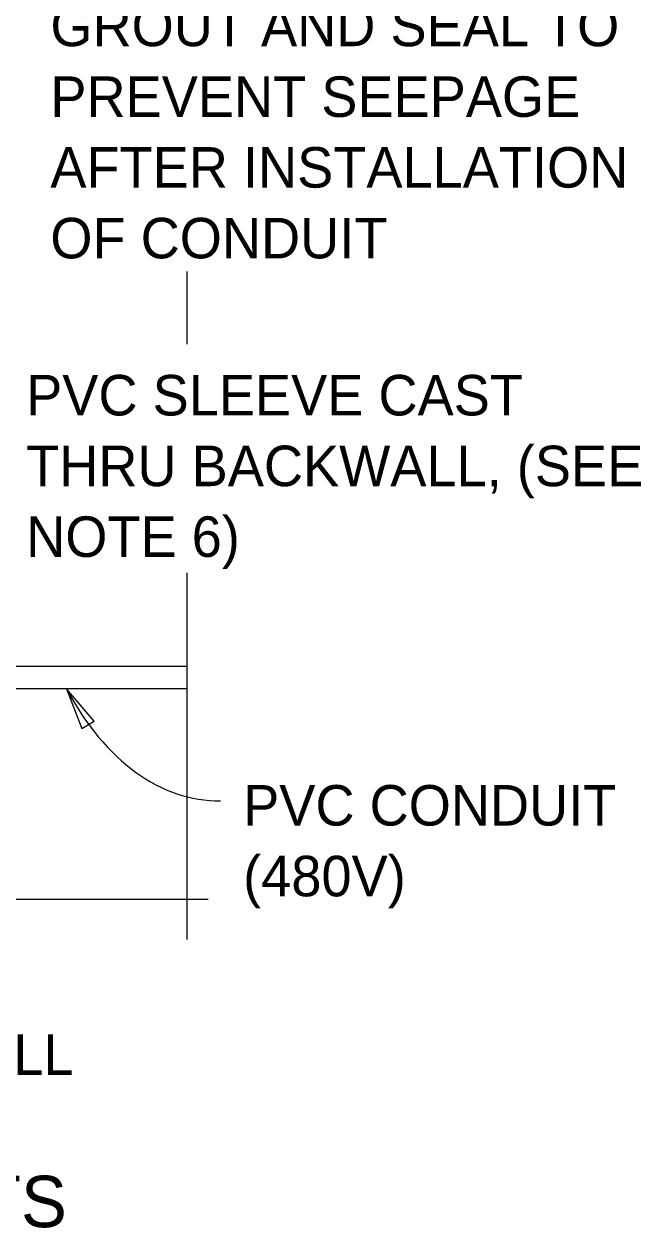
# Model space of a CAD drawing. Extents: x -1660015.2 to -1659984.9, y 2580594.2 to 2580616.7.
# Drawn here: x -1659987.255 to -1659984.953, y 2580606.68 to 2580611.174 of the extents above; entities that cross this region are included whole.
import ezdxf

# ---------------------------------------------------------------- set-up
doc = ezdxf.new("R2010")
doc.units = 0
for name, color, linetype in [('Default', 7, 'Continuous'), ('PlotBorder_dp', 7, 'Continuous'), ('SheetLines_dp', 7, 'Continuous')]:
    doc.layers.add(name, color=color, linetype=linetype)

msp = doc.modelspace()

# ---------------------------------------------------------------- linework, layer by layer
at = {"layer": 'Default'}
for p, q in [((-1659986.6456, 2580608.7761), (-1659989.7604, 2580608.7761)), ((-1659986.6456, 2580608.6928), (-1659989.7604, 2580608.6928))]:
    msp.add_line(p, q, dxfattribs=at)
at = {"layer": 'SheetLines_dp'}
for points in [[(-1659986.6457, 2580609.9792), (-1659986.6457, 2580610.2508)], [(-1659986.6457, 2580607.7573), (-1659986.6457, 2580609.1252)], [(-1659986.5682, 2580607.9066), (-1659989.8898, 2580607.9066), (-1659989.8898, 2580607.9841), (-1659989.9235, 2580607.9066), (-1659989.9573, 2580607.8291), (-1659989.9573, 2580607.9066), (-1659994.3703, 2580607.9066)]]:
    msp.add_lwpolyline(points, dxfattribs=at)
msp.add_lwpolyline([(-1659987.0965, 2580608.6927), (-1659987.039, 2580608.5451), (-1659986.9936, 2580608.5723)], close=True, dxfattribs=at)
msp.add_ellipse((-1659986.5418, 2580609.4132), major_axis=(-0.0198, 1.1382), ratio=0.637727, start_param=2.244978, end_param=3.14156, dxfattribs=at)

# ---------------------------------------------------------------- texts
at = {"layer": 'PlotBorder_dp'}
msp.add_text('CONCRETE BOX GIRDER BRIDGE SECTION THRU END BENTS', height=0.192, dxfattribs=at).set_placement((-1659994.8125, 2580606.6832))
at = {"layer": 'SheetLines_dp'}
for s, p in [('GROUT AND SEAL TO ', (-1659987.1566, 2580611.0916)), ('PREVENT SEEPAGE ', (-1659987.1566, 2580610.8276)), ('AFTER INSTALLATION ', (-1659987.1566, 2580610.5636)), ('OF CONDUIT', (-1659987.1566, 2580610.2996)), ('PVC SLEEVE CAST', (-1659987.247, 2580609.7132)), ('THRU BACKWALL, (SEE ', (-1659987.247, 2580609.4492)), ('NOTE 6)', (-1659987.247, 2580609.1852)), ('PVC CONDUIT', (-1659986.4371, 2580608.1823)), ('(480V)', (-1659986.4371, 2580607.9183)), ('END BENT BACKWALL', (-1659989.2495, 2580607.2516))]:
    msp.add_text(s, height=0.1512, dxfattribs=at).set_placement(p)

doc.saveas('drawing.dxf')
